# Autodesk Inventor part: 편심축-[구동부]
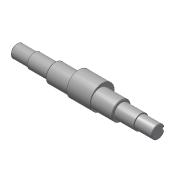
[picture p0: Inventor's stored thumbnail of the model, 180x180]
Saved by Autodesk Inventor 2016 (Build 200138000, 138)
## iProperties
Created: 2015-10
Part Number: 편심축-[구동부]
Document SubType Name: Modeling
Designer: mdu
Density: 7.86 g/cm^3
Material: 강철, 연강
Mass: 1327.93 g
Surface Area: 248.524 cm^2
Volume: 168.947 cm^3
Appearance: 강철
Author: mdu
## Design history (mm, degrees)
sketch "스케치1"
  geometry: L1 (-20.5, -41.331)-(-20.5, 32.669) reference; L2 (7.5, -30.031)-(7.5, 21.369) reference; L3 (135.5, -30.331)-(135.5, 21.669) reference; L4 (121.5, 21.369)-(121.5, -30.031) reference; L5 (184.5, -4.331)-(-57.5, -4.331); L6 (184.5, -4.331)-(184.5, 6.669); L7 (154.5, 8.169)-(121.5, 8.169); L8 (121.5, 8.169)-(121.5, 11.669); L9 (121.5, 11.669)-(7.5, 11.669); L10 (7.5, 11.669)-(7.5, 8.169); L11 (7.5, 8.169)-(-27.5, 8.169); L12 (-27.5, 8.169)-(-27.5, 6.669); L13 (-27.5, 6.669)-(-57.5, 6.669); L14 (-57.5, 6.669)-(-57.5, -4.331); L15 (154.5, 8.169)-(154.5, 6.669); L16 (154.5, 6.669)-(184.5, 6.669); C1 r 32.5 at (64.5, -4.331) reference; 1 further point
  constraints: 24 end point, 8 perpendicular, 5 point on line, 3 parallel, 2 collinear
  dimensions: "d1" = 25 diameter of L11 L5; "d2" = 32 diameter of L9 L5; "d3" = 22 diameter of L13 L5; "d4" = 35 distance of L10.end L11.end; "d5" = 30 distance of L12.end L13.end; "d15" = 33 distance of L7.start L7.end; "d26" = 30 distance of L15.end L6.end
revolve "회전1" sketch "스케치1" stored, may be unused: angle "d6" = 90 deg
node "작업 평면1"
sketch "스케치2"
  geometry: C1 r 16 at (0, 0) reference; C2 r 16 at (0, 0) reference; C3 r 20.75 at (0, 4); C4 r 16 at (0, 0) reference; 1 further point
  constraints: 1 centre point, 1 vertical alignment
  dimensions: "d8" = 41.5 diameter of C3; "d25" = 4 distance of C3.centre C1.centre
extrude "돌출1" join sketch "스케치2" stored distance "d9" = 40; taper "d10" = 0 deg
chamfer "모따기1" distance "d11" = 1; stored, may be unused: second distance "d12" = 2, angle "d13" = 45 deg
node "작업 평면2"
sketch "스케치3"
  geometry: L1 (-15, -10)-(-15, 10) reference; L2 (-15, 3)-(0, 3); L3 (0, -3)-(-15, -3); A1 r 3 centre (0, 0) between (0, -3) and (0, 3); 2 further points
  constraints: 4 end point, 2 perpendicular, 2 point on circle, 2 point on line, 2 tangent, 1 centre point, 1 horizontal alignment, 1 midpoint
  dimensions: "d16" = 18 dimension on A1 L1; "d17" = 6 distance between parallel lines of L3 L2
extrude "돌출2" cut sketch "스케치3" distance "d18" = 3.5; taper "d19" = 0 deg
node "작업 평면3"
node "솔리드1"
mirror "대칭1"
node "참조1"
node "참조2"
node "참조3"
node "참조4"
node "참조5"
node "투영된 루프1"
